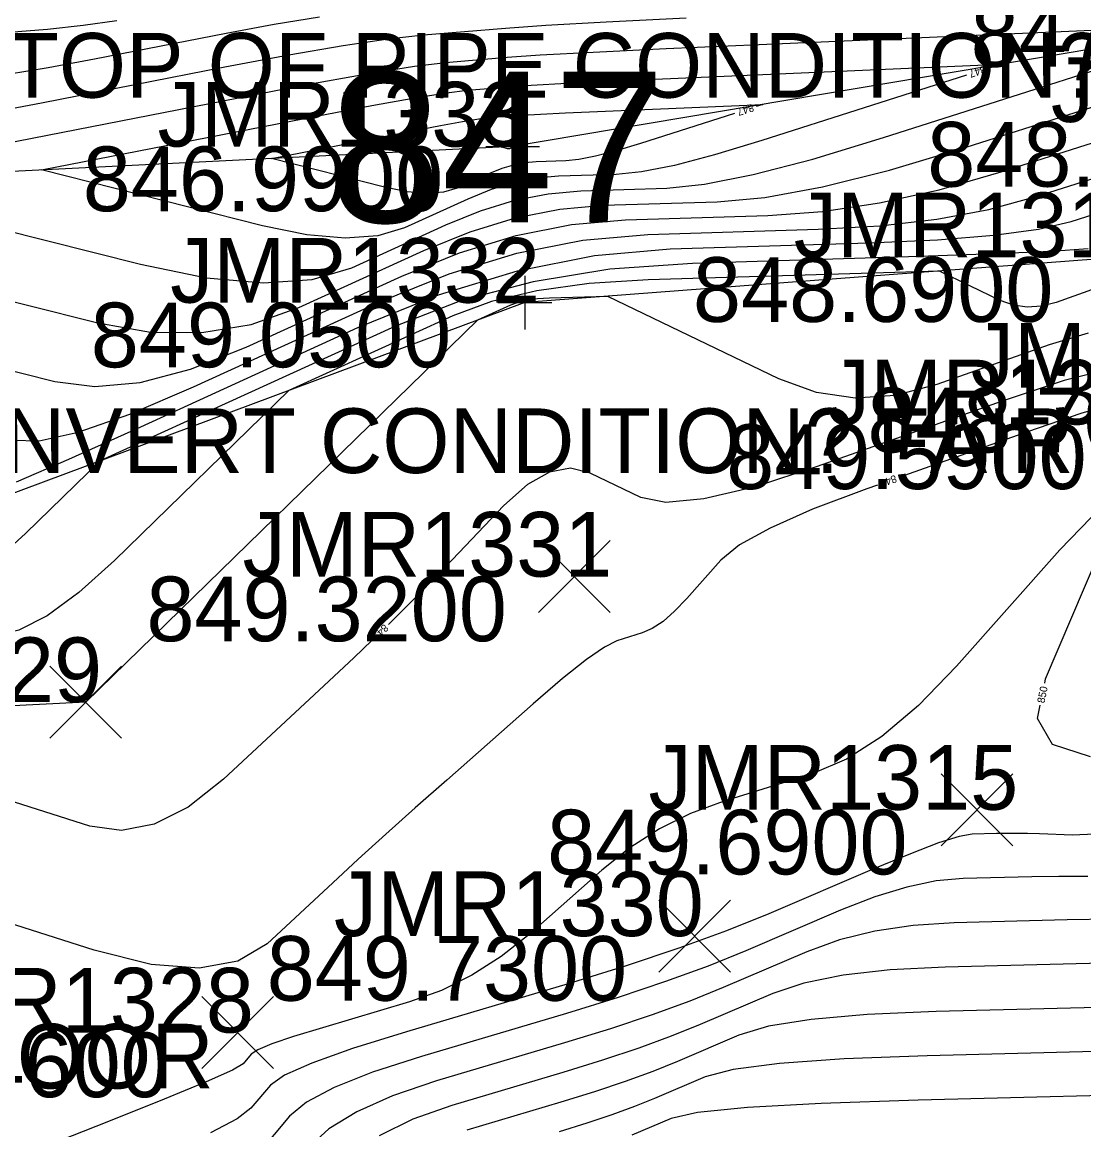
# Model space of a CAD drawing. Extents: x 1654928 to 1810050, y 486881 to 626330.
# Drawn here: x 1801494.41 to 1801514.13, y 489824.51 to 489845.07 of the extents above; entities that cross this region are included whole.
import ezdxf

# ---------------------------------------------------------------- set-up
doc = ezdxf.new("R2010")
doc.units = 0
for name, color, linetype in [('DR_X_Ditch', 7, 'Continuous'), ('DT_X_Contour_Major', 7, 'Continuous'), ('DT_X_Contour_Minor', 7, 'Continuous'), ('SV_X_Random_Point', 7, 'Continuous'), ('SV_X_Shot_Marker', 7, 'Continuous'), ('SV_X_Text_Comment', 7, 'Continuous'), ('SV_X_Text_Elevation', 7, 'Continuous'), ('SV_X_Text_Name', 7, 'Continuous'), ('SV_X_Toe_of_Slope', 7, 'Continuous')]:
    doc.layers.add(name, color=color, linetype=linetype)

msp = doc.modelspace()

# ---------------------------------------------------------------- linework, layer by layer
at = {"layer": 'DR_X_Ditch'}
msp.add_lwpolyline([(1801538.429, 489841.719), (1801527.515, 489844.014), (1801519.444, 489845.441), (1801503.521, 489842.761), (1801490.506, 489842.113), (1801478.561, 489839.498), (1801468.658, 489833.373), (1801465.597, 489830.762), (1801453.487, 489824.594)], dxfattribs=at)
at = {"layer": 'DT_X_Contour_Major'}
for points in [[(1801499.935, 489845.16), (1801499.095, 489845.026), (1801498.204, 489844.861), (1801495.758, 489844.383), (1801494.894, 489844.222), (1801494.138, 489844.097)], [(1801493.175, 489838.864), (1801495.021, 489838.398), (1801495.762, 489838.307), (1801496.601, 489838.383), (1801497.538, 489838.626), (1801498.573, 489839.036), (1801501.464, 489840.353), (1801502.536, 489840.789), (1801503.585, 489841.108), (1801504.612, 489841.312), (1801505.615, 489841.4), (1801508.259, 489841.48), (1801509.274, 489841.553), (1801510.334, 489841.713), (1801511.441, 489841.958), (1801512.593, 489842.29), (1801515.728, 489843.29)], [(1801503.308, 489842.751), (1801503.477, 489842.783), (1801503.491, 489842.786), (1801503.53, 489842.789), (1801503.596, 489842.792), (1801503.743, 489842.799), (1801503.634, 489842.764), (1801503.595, 489842.753), (1801503.568, 489842.749), (1801503.542, 489842.748), (1801503.532, 489842.747), (1801503.522, 489842.745), (1801503.512, 489842.742), (1801503.501, 489842.737), (1801503.472, 489842.724), (1801503.46, 489842.721), (1801503.446, 489842.72), (1801503.428, 489842.721), (1801503.408, 489842.725), (1801503.308, 489842.751)], [(1801514.207, 489839.296), (1801513.482, 489839.083), (1801511.395, 489838.343), (1801510.625, 489838.142), (1801509.881, 489838.092), (1801509.161, 489838.193), (1801508.467, 489838.446), (1801505.286, 489839.98), (1801504.204, 489839.947), (1801503.985, 489839.934), (1801503.791, 489839.907), (1801503.622, 489839.867), (1801503.479, 489839.814), (1801502.87, 489839.537), (1801495.594, 489832.449), (1801492.521, 489832.293), (1801491.824, 489832.236), (1801491.051, 489832.135), (1801490.201, 489831.987), (1801489.275, 489831.794), (1801486.705, 489831.22), (1801485.747, 489831.001), (1801485.327, 489830.9)], [(1801514.203, 489829.213), (1801513.661, 489829.214), (1801513.162, 489829.207), (1801511.886, 489829.174), (1801511.385, 489829.128), (1801510.839, 489829.014), (1801510.248, 489828.833), (1801509.611, 489828.585), (1801507.854, 489827.833), (1801507.151, 489827.549), (1801506.361, 489827.26), (1801505.483, 489826.968), (1801504.518, 489826.67), (1801501.828, 489825.872), (1801500.918, 489825.579), (1801500.207, 489825.296), (1801499.694, 489825.024), (1801499.38, 489824.763), (1801498.806, 489824.082)], [(1801516.442, 489825.197), (1801511.052, 489825.058), (1801509.25, 489824.998), (1801507.884, 489824.922), (1801506.955, 489824.829), (1801506.463, 489824.72), (1801505.733, 489824.408)]]:
    msp.add_lwpolyline(points, dxfattribs=at)
at = {"layer": 'DT_X_Contour_Minor'}
for points in [[(1801496.168, 489845.096), (1801495.545, 489845.009), (1801494.88, 489844.936), (1801494.171, 489844.877), (1801492.224, 489844.739), (1801491.502, 489844.704), (1801490.794, 489844.705), (1801490.102, 489844.74), (1801489.425, 489844.811), (1801487.639, 489845.044), (1801487.011, 489845.114)], [(1801506.743, 489845.141), (1801505.258, 489845.069), (1801504.139, 489845.006), (1801503.387, 489844.954), (1801501.868, 489844.828), (1801501.209, 489844.755), (1801500.374, 489844.632), (1801499.363, 489844.458), (1801498.174, 489844.234), (1801494.769, 489843.568), (1801493.621, 489843.348)], [(1801496.608, 489840.575), (1801497.834, 489840.323), (1801498.897, 489840.229), (1801499.797, 489840.292), (1801500.533, 489840.512), (1801502.279, 489841.307), (1801502.926, 489841.57), (1801503.56, 489841.763), (1801504.18, 489841.886), (1801504.786, 489841.939), (1801506.383, 489841.988), (1801507.084, 489842.06), (1801507.988, 489842.24), (1801509.097, 489842.529), (1801510.41, 489842.926), (1801517.011, 489845.031), (1801508.098, 489844.648), (1801506.373, 489844.572), (1801505.018, 489844.507), (1801504.034, 489844.454), (1801503.42, 489844.412), (1801502.276, 489844.317), (1801501.696, 489844.246), (1801500.814, 489844.104), (1801499.63, 489843.891), (1801498.144, 489843.606), (1801490.506, 489842.113)], [(1801494.773, 489842.326), (1801499.907, 489843.329), (1801500.906, 489843.52), (1801501.702, 489843.664), (1801502.294, 489843.759), (1801502.684, 489843.807), (1801503.453, 489843.871), (1801503.866, 489843.899), (1801504.528, 489843.935), (1801505.438, 489843.978), (1801506.597, 489844.029), (1801512.588, 489844.287), (1801512.35, 489844.211)], [(1801511.95, 489844.084), (1801508.151, 489842.872), (1801507.269, 489842.605), (1801506.524, 489842.411), (1801505.916, 489842.29), (1801505.445, 489842.241), (1801504.371, 489842.209), (1801503.964, 489842.173), (1801503.547, 489842.09), (1801503.121, 489841.961), (1801502.686, 489841.784), (1801501.513, 489841.249), (1801501.018, 489841.102), (1801500.413, 489841.059), (1801499.699, 489841.123), (1801498.875, 489841.292), (1801494.773, 489842.326)], [(1801493.148, 489840.159), (1801495.815, 489839.486), (1801496.798, 489839.315), (1801497.749, 489839.306), (1801498.667, 489839.459), (1801499.553, 489839.774), (1801501.871, 489840.83), (1801502.731, 489841.179), (1801503.573, 489841.436), (1801504.396, 489841.599), (1801505.2, 489841.67), (1801507.321, 489841.734), (1801508.206, 489841.815), (1801509.272, 489842.012), (1801510.518, 489842.323), (1801511.944, 489842.749), (1801515.988, 489844.039)], [(1801499.041, 489842.538), (1801501.67, 489843.052), (1801502.182, 489843.15), (1801502.589, 489843.224), (1801502.893, 489843.273), (1801503.093, 489843.297), (1801503.486, 489843.33), (1801503.698, 489843.344), (1801504.037, 489843.362), (1801504.503, 489843.385), (1801505.097, 489843.411), (1801508.165, 489843.543), (1801508.043, 489843.504)], [(1801507.643, 489843.376), (1801505.893, 489842.818), (1801505.441, 489842.681), (1801505.059, 489842.582), (1801504.748, 489842.52), (1801504.506, 489842.495), (1801503.957, 489842.478), (1801503.748, 489842.46), (1801503.535, 489842.418), (1801503.317, 489842.351), (1801503.094, 489842.261), (1801502.493, 489841.987), (1801502.239, 489841.911), (1801501.929, 489841.89), (1801501.564, 489841.922), (1801501.141, 489842.009), (1801499.041, 489842.538)], [(1801494.227, 489837.31), (1801494.726, 489837.299), (1801495.453, 489837.46), (1801496.409, 489837.793), (1801497.593, 489838.299), (1801501.056, 489839.876), (1801502.341, 489840.398), (1801503.598, 489840.781), (1801504.827, 489841.025), (1801506.029, 489841.131), (1801509.197, 489841.227), (1801510.341, 489841.291), (1801511.397, 489841.414), (1801512.364, 489841.593), (1801513.243, 489841.831), (1801515.469, 489842.541)], [(1801470.579, 489833.827), (1801471.437, 489834.342), (1801472.576, 489835.042), (1801475.989, 489837.152), (1801477.113, 489837.849), (1801478.433, 489838.669), (1801478.628, 489838.793), (1801478.735, 489838.87), (1801478.989, 489838.955), (1801479.672, 489839.152), (1801480.783, 489839.462), (1801482.322, 489839.883), (1801490.506, 489842.113), (1801496.608, 489840.575)], [(1801494.305, 489836.537), (1801495.28, 489836.96), (1801496.614, 489837.561), (1801500.649, 489839.399), (1801502.146, 489840.007), (1801503.611, 489840.454), (1801505.043, 489840.738), (1801506.444, 489840.861), (1801510.135, 489840.973), (1801511.408, 489841.029), (1801512.459, 489841.114), (1801513.287, 489841.229), (1801513.892, 489841.372), (1801515.21, 489841.792)], [(1801514.21, 489840.864), (1801513.521, 489840.815), (1801512.476, 489840.767), (1801511.073, 489840.719), (1801506.858, 489840.592), (1801505.328, 489840.483), (1801503.9, 489840.252), (1801502.572, 489839.9), (1801501.347, 489839.426), (1801495.863, 489836.928), (1801494.474, 489835.575), (1801494.191, 489835.32)], [(1801514.354, 489840.13), (1801513.614, 489839.868), (1801513.34, 489839.796), (1801513.076, 489839.778), (1801512.821, 489839.814), (1801512.575, 489839.904), (1801511.446, 489840.448), (1801506.037, 489840.285), (1801504.941, 489840.217), (1801503.972, 489840.084), (1801503.129, 489839.885), (1801502.413, 489839.62), (1801499.366, 489838.232), (1801496.125, 489835.075), (1801495.465, 489834.48), (1801494.874, 489834.049), (1801494.351, 489833.782), (1801493.898, 489833.679), (1801492.78, 489833.622), (1801492.242, 489833.565), (1801491.465, 489833.437), (1801491.377, 489833.419)], [(1801514.648, 489838.641), (1801513.763, 489838.415), (1801512.609, 489838.036), (1801509.177, 489836.819), (1801508.006, 489836.441), (1801507.07, 489836.22), (1801506.367, 489836.155), (1801505.899, 489836.246), (1801504.96, 489836.699), (1801504.596, 489836.788), (1801504.208, 489836.718), (1801503.796, 489836.488), (1801503.359, 489836.098), (1801502.162, 489834.844), (1801501.685, 489834.356), (1801501.216, 489833.89)], [(1801514.814, 489838.022), (1801514.075, 489837.803), (1801513.083, 489837.465), (1801510.693, 489836.618)], [(1801510.297, 489836.478), (1801510.099, 489836.408), (1801509.091, 489836.028), (1801508.302, 489835.68), (1801507.735, 489835.365), (1801507.388, 489835.083), (1801506.756, 489834.374), (1801506.527, 489834.134), (1801506.313, 489833.947), (1801506.113, 489833.813), (1801505.928, 489833.732), (1801505.456, 489833.586), (1801505.226, 489833.471), (1801504.89, 489833.238), (1801504.447, 489832.886), (1801503.899, 489832.416), (1801502.296, 489831.002), (1801501.713, 489830.485), (1801501.166, 489829.995), (1801500.655, 489829.531), (1801500.18, 489829.094), (1801498.961, 489827.963), (1801498.418, 489827.638), (1801497.701, 489827.51), (1801496.81, 489827.579), (1801495.747, 489827.846), (1801492.68, 489828.82)], [(1801514.266, 489835.872), (1801513.682, 489835.272), (1801511.764, 489833.118), (1801511.057, 489832.387), (1801510.375, 489831.81), (1801509.718, 489831.387), (1801509.085, 489831.118), (1801507.432, 489830.605), (1801506.826, 489830.381), (1801506.248, 489830.093), (1801505.699, 489829.742), (1801505.178, 489829.327), (1801503.828, 489828.136), (1801503.309, 489827.723), (1801502.765, 489827.377), (1801502.197, 489827.097), (1801501.603, 489826.884), (1801499.988, 489826.405), (1801499.451, 489826.239), (1801499.052, 489826.102), (1801498.79, 489825.993), (1801498.665, 489825.913), (1801498.517, 489825.736), (1801498.317, 489825.619), (1801497.828, 489825.399), (1801497.052, 489825.077), (1801495.987, 489824.653), (1801492.762, 489823.385)], [(1801513.402, 489832.802), (1801513.418, 489832.88), (1801514.391, 489835.17)], [(1801500.914, 489833.598), (1801500.57, 489833.267), (1801499.931, 489832.668), (1801498.153, 489831.019), (1801497.498, 489830.501), (1801496.866, 489830.183), (1801496.257, 489830.065), (1801495.67, 489830.147), (1801494.137, 489830.634)], [(1801514.252, 489831.432), (1801513.546, 489831.663), (1801513.268, 489832.146), (1801513.318, 489832.39)], [(1801514.335, 489829.994), (1801513.92, 489829.978), (1801513.306, 489830), (1801513.083, 489830.007), (1801512.875, 489830.011), (1801512.683, 489830.011), (1801512.506, 489830.009), (1801512.053, 489829.997), (1801511.812, 489829.954), (1801511.43, 489829.833), (1801510.907, 489829.634), (1801510.241, 489829.358), (1801508.278, 489828.518), (1801507.493, 489828.201), (1801506.61, 489827.878), (1801505.63, 489827.551), (1801504.552, 489827.219), (1801501.547, 489826.328), (1801500.544, 489826.016), (1801499.789, 489825.746), (1801499.282, 489825.521), (1801499.023, 489825.338), (1801498.661, 489824.909), (1801498.406, 489824.715), (1801497.912, 489824.454)], [(1801514.64, 489828.418), (1801513.818, 489828.405), (1801511.719, 489828.351), (1801510.958, 489828.302), (1801510.248, 489828.196), (1801509.589, 489828.033), (1801508.982, 489827.812), (1801507.43, 489827.148), (1801506.809, 489826.897), (1801506.111, 489826.642), (1801505.336, 489826.384), (1801504.484, 489826.121), (1801502.108, 489825.417), (1801501.292, 489825.142), (1801500.625, 489824.845), (1801500.106, 489824.528), (1801499.737, 489824.188)], [(1801514.474, 489827.603), (1801511.553, 489827.528), (1801510.531, 489827.476), (1801509.657, 489827.377), (1801508.931, 489827.232), (1801508.352, 489827.039), (1801507.006, 489826.463), (1801506.467, 489826.245), (1801505.862, 489826.024), (1801505.189, 489825.8), (1801504.45, 489825.572), (1801502.389, 489824.961), (1801501.666, 489824.705), (1801501.043, 489824.395)], [(1801515.13, 489826.801), (1801511.386, 489826.705), (1801510.104, 489826.65), (1801509.066, 489826.559), (1801508.272, 489826.431), (1801507.722, 489826.266), (1801506.581, 489825.778), (1801506.125, 489825.594), (1801505.612, 489825.406), (1801505.042, 489825.216), (1801504.416, 489825.023), (1801502.67, 489824.505)], [(1801515.786, 489825.999), (1801511.219, 489825.881), (1801509.677, 489825.824), (1801508.475, 489825.74), (1801507.614, 489825.63), (1801507.093, 489825.493), (1801506.157, 489825.093), (1801505.783, 489824.942), (1801505.363, 489824.788), (1801504.896, 489824.632), (1801504.382, 489824.474)]]:
    msp.add_lwpolyline(points, dxfattribs=at)
at = {"layer": 'SV_X_Random_Point'}
for p, q in [((1801503.999, 489834.11), (1801505.332, 489835.445)), ((1801503.999, 489835.445), (1801505.332, 489834.11)), ((1801494.927, 489831.781), (1801496.26, 489833.116)), ((1801494.927, 489833.116), (1801496.26, 489831.781)), ((1801511.478, 489829.782), (1801512.811, 489831.117)), ((1801511.478, 489831.117), (1801512.811, 489829.782)), ((1801506.233, 489827.437), (1801507.567, 489828.772)), ((1801506.233, 489828.772), (1801507.567, 489827.437)), ((1801497.749, 489825.648), (1801499.082, 489826.983)), ((1801497.749, 489826.983), (1801499.082, 489825.648))]:
    msp.add_line(p, q, dxfattribs=at)
at = {"layer": 'SV_X_Shot_Marker'}
for p, q in [((1801503.521, 489843.261), (1801503.521, 489842.261)), ((1801503.021, 489842.761), (1801504.021, 489842.761)), ((1801503.521, 489842.761), (1801503.521, 489842.761)), ((1801503.746, 489840.363), (1801503.746, 489839.363)), ((1801503.246, 489839.863), (1801504.246, 489839.863)), ((1801503.746, 489839.863), (1801503.746, 489839.863))]:
    msp.add_line(p, q, dxfattribs=at)
at = {"layer": 'SV_X_Toe_of_Slope'}
msp.add_lwpolyline([(1801548.771, 489840.76), (1801538.587, 489838.29), (1801528.242, 489840.124), (1801519.185, 489843.217), (1801514.834, 489840.706), (1801503.746, 489839.863), (1801493.235, 489835.949), (1801481.982, 489831.828), (1801478.469, 489833.99), (1801472.566, 489830.006), (1801464.849, 489824.991), (1801462.27, 489825.427), (1801460.621, 489820.525)], dxfattribs=at)

# ---------------------------------------------------------------- texts
at = {"layer": 'DT_X_Contour_Major'}
msp.add_text('847', height=2.8, dxfattribs=at).set_placement((1801500.112, 489841.351))
at = {"layer": 'DT_X_Contour_Minor'}
for s, rotation, p in [('847', 197.6884, (1801512.281, 489844.263)), ('847', 197.6884, (1801507.974, 489843.555)), ('849', 199.5128, (1801510.623, 489836.668)), ('849', 224.0633, (1801501.132, 489833.906)), ('850', 78.4006, (1801513.396, 489832.42))]:
    msp.add_text(s, height=0.14, rotation=rotation, dxfattribs=at).set_placement(p)
at = {"layer": 'SV_X_Text_Comment'}
for s, p in [('EL*CMP FD0 SIZE? 0.50 LOCATION? TOP OF PIPE CONDITION? FAIR', (1801466.022, 489843.668)), ('BL*CMP SIZE? 0.50 LOCATION? INVERT CONDITION? FAIR', (1801468.998, 489836.7)), ('BL*RCP SIZE? 4.50 LOCATION? INVERT CONDITION? POOR', (1801452.136, 489825.277))]:
    msp.add_text(s, height=1.2, dxfattribs=at).set_placement(p)
at = {"layer": 'SV_X_Text_Elevation'}
for s, p in [('847.7100', (1801512.027, 489844.241)), ('848.6300', (1801511.22, 489842.017)), ('846.9900', (1801495.538, 489841.561)), ('848.6900', (1801506.869, 489839.506)), ('849.0500', (1801495.687, 489838.663)), ('848.7000', (1801510.109, 489837.084)), ('849.5900', (1801507.487, 489836.403)), ('849.3200', (1801496.72, 489833.578)), ('849.6900', (1801504.161, 489829.25)), ('849.7300', (1801498.954, 489826.905)), ('849.4600', (1801490.441, 489825.115))]:
    msp.add_text(s, height=1.2, dxfattribs=at).set_placement(p)
at = {"layer": 'SV_X_Text_Name'}
for s, p in [('JMR1311', (1801513.516, 489843.217)), ('JMR1333', (1801496.927, 489842.761)), ('JMR1312', (1801508.741, 489840.706)), ('JMR1332', (1801497.161, 489839.863)), ('JMR1313', (1801512.028, 489838.284)), ('JMR1314', (1801509.358, 489837.603)), ('JMR1331', (1801498.505, 489834.778)), ('JMR1329', (1801489.028, 489832.449)), ('JMR1315', (1801506.042, 489830.45)), ('JMR1330', (1801500.202, 489828.105)), ('JMR1328', (1801491.849, 489826.315))]:
    msp.add_text(s, height=1.2, dxfattribs=at).set_placement(p)

doc.saveas('drawing.dxf')
